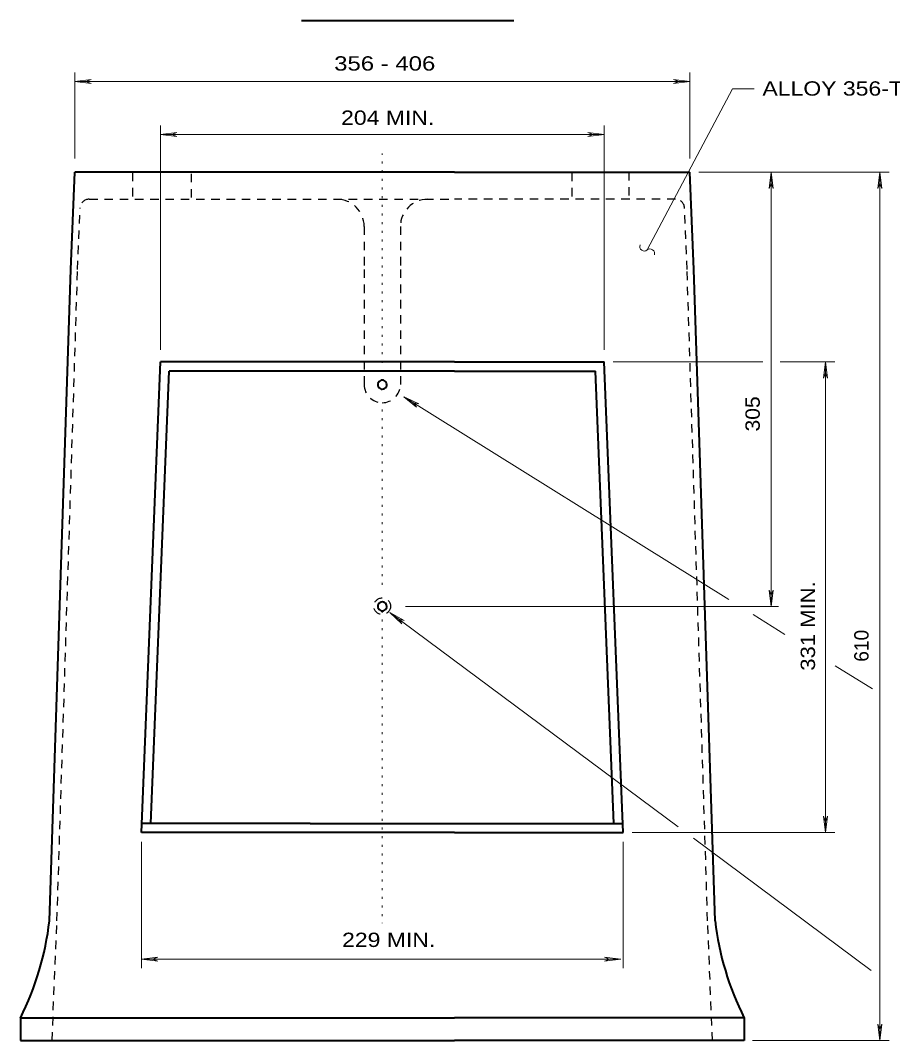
# Model space of a CAD drawing. Extents: x 312583 to 312854, y 144419 to 144597.
# Drawn here: x 312715.4 to 312761.7, y 144485 to 144539.1 of the extents above; entities that cross this region are included whole.
import ezdxf

# ---------------------------------------------------------------- set-up
doc = ezdxf.new("R2010")
doc.units = 0
doc.header["$LTSCALE"] = 0.3
doc.linetypes.add('DOTTED', pattern=[1.5, 0.3, -1.2])
doc.linetypes.add('SHORT_DASHED', pattern=[2.7, 1.5, -1.2])
doc.layers.add('1', color=7, linetype='Continuous', lineweight=40)
doc.layers.add('2', color=7, linetype='Continuous', lineweight=13)

msp = doc.modelspace()

# ---------------------------------------------------------------- linework, layer by layer
at = {"layer": '1'}
for p, q in [((312738.4, 144531.0452), (312718.2444, 144531.0452)), ((312738.4, 144531.0452), (312750.889, 144531.0452)), ((312721.7864, 144495.9932), (312722.7984, 144520.9712)), ((312738.4, 144520.9712), (312722.7984, 144520.9712)), ((312738.4, 144520.9712), (312746.335, 144520.9712)), ((312747.3547, 144495.9932), (312746.335, 144520.9712)), ((312722.2847, 144496.4686), (312723.2584, 144520.4882)), ((312738.4, 144520.4882), (312723.2584, 144520.4882)), ((312738.4, 144520.4882), (312745.875, 144520.4882)), ((312746.8487, 144496.4686), (312745.875, 144520.4882)), ((312730.7334, 144496.4686), (312721.8017, 144496.4686)), ((312730.7334, 144496.4686), (312747.3317, 144496.4686)), ((312738.4, 144495.9932), (312721.7864, 144495.9932)), ((312738.4, 144495.9932), (312747.3547, 144495.9932)), ((312715.3617, 144486.1569), (312715.3617, 144484.9532)), ((312715.3617, 144486.1569), (312738.4, 144486.1569)), ((312753.7717, 144486.1569), (312738.4, 144486.1569)), ((312753.7717, 144486.1569), (312753.7717, 144484.9532)), ((312715.3617, 144484.9532), (312738.4, 144484.9532)), ((312753.7717, 144484.9532), (312738.4, 144484.9532))]:
    msp.add_line(p, q, dxfattribs=at)
at = {"layer": '1', "linetype": 'SHORT_DASHED', "lineweight": 25}
for p, q in [((312721.265, 144531.0146), (312721.265, 144531.0452)), ((312721.311, 144531.0146), (312721.311, 144529.6116)), ((312724.4314, 144530.9609), (312724.4314, 144529.6116)), ((312744.6254, 144531.0146), (312744.6254, 144529.6116)), ((312747.646, 144531.0606), (312747.646, 144529.6116)), ((312719.011, 144529.6116), (312738.4, 144529.6116)), ((312750.13, 144529.6116), (312738.4, 144529.6116)), ((312718.3977, 144525.8856), (312718.528, 144529.1439)), ((312750.7434, 144525.8856), (312750.6054, 144529.1439))]:
    msp.add_line(p, q, dxfattribs=at)
at = {"layer": '1'}
for points in [[(312716.9027, 144491.3166), (312718.0374, 144525.8856), (312718.2444, 144531.0452)], [(312752.2307, 144491.3166), (312751.1037, 144525.8856), (312750.889, 144531.0452)]]:
    msp.add_lwpolyline(points, dxfattribs=at)
at = {"layer": '1', "linetype": 'SHORT_DASHED', "lineweight": 25}
for points in [[(312733.6084, 144528.1626), (312733.6084, 144525.8856), (312733.6084, 144519.7676)], [(312735.5327, 144528.1626), (312735.5327, 144525.8856), (312735.5327, 144519.7676)], [(312717.0407, 144484.9532), (312717.3014, 144491.3166), (312718.3977, 144525.8856)], [(312752.0927, 144484.9532), (312751.832, 144491.3166), (312750.7434, 144525.8856)]]:
    msp.add_lwpolyline(points, dxfattribs=at)
msp.add_circle((312734.5629, 144508.0069), 0.4408, dxfattribs=at)
for centre, radius, start, end in [((312719.0069, 144529.126), 0.4804, 90, 177.67414), ((312732.1656, 144528.1652), 1.4411, 0, 90), ((312736.9694, 144528.1652), 1.4411, 90, 180), ((312750.1281, 144529.126), 0.4804, 2.32586, 90), ((312734.5675, 144519.7682), 0.9608, 180, 270), ((312734.5648, 144519.7676), 0.9608, 270.11436, 0)]:
    msp.add_arc(centre, radius, start, end, dxfattribs=at)
at = {"layer": '1'}
for centre, radius, start, end in [((312734.5667, 144519.7676), 0.2402, 89.54164, 270.45836), ((312734.5667, 144519.7676), 0.2402, 270.45836, 91.37507), ((312734.5667, 144507.9973), 0.2402, 89.08692, 270.00364), ((312734.5667, 144507.9973), 0.2402, 270.00364, 90.92035), ((312701.6269, 144493.0588), 15.3723, 333.3018, 353.48942), ((312767.5065, 144493.0588), 15.3723, 186.51058, 206.6982)]:
    msp.add_arc(centre, radius, start, end, dxfattribs=at)
at = {"layer": '2', "lineweight": 40}
msp.add_line((312730.2713, 144539.099), (312741.5499, 144539.099), dxfattribs=at)
at = {"layer": '2'}
for p, q in [((312718.2444, 144531.7736), (312718.2444, 144536.3352)), ((312750.889, 144531.7736), (312750.889, 144536.3352)), ((312718.2444, 144535.8522), (312719.1107, 144535.9596)), ((312718.2444, 144535.8522), (312719.1107, 144535.7449)), ((312718.2444, 144535.8522), (312738.8754, 144535.8522)), ((312719.1107, 144535.9596), (312718.8347, 144535.8522)), ((312719.1107, 144535.7449), (312718.8347, 144535.8522)), ((312738.4, 144535.8522), (312750.889, 144535.8522)), ((312750.0227, 144535.9596), (312750.2987, 144535.8522)), ((312750.889, 144535.8522), (312750.0227, 144535.9596)), ((312750.0227, 144535.7449), (312750.2987, 144535.8522)), ((312750.889, 144535.8522), (312750.0227, 144535.7449)), ((312753.157, 144535.4673), (312748.6274, 144526.9206)), ((312753.157, 144535.4673), (312754.2993, 144535.4673)), ((312722.7984, 144533.0386), (312723.6647, 144533.1459)), ((312722.7984, 144533.0386), (312723.6647, 144532.9312)), ((312723.6647, 144533.1459), (312723.3887, 144533.0386)), ((312723.6647, 144532.9312), (312723.3887, 144533.0386)), ((312745.4687, 144533.1459), (312745.7447, 144533.0386)), ((312746.335, 144533.0386), (312745.4687, 144533.1459)), ((312745.4687, 144532.9312), (312745.7447, 144533.0386)), ((312746.335, 144533.0386), (312745.4687, 144532.9312)), ((312751.372, 144531.0452), (312761.4614, 144531.0452)), ((312755.213, 144531.0452), (312755.1057, 144530.1789)), ((312755.213, 144531.0452), (312755.3204, 144530.1789)), ((312760.9784, 144531.0452), (312760.871, 144530.1789)), ((312760.9784, 144531.0452), (312761.0857, 144530.1789)), ((312760.9784, 144525.8856), (312760.9784, 144531.0452)), ((312755.1057, 144530.1789), (312755.213, 144530.4549)), ((312755.3204, 144530.1789), (312755.213, 144530.4549)), ((312760.871, 144530.1789), (312760.9784, 144530.4549)), ((312761.0857, 144530.1789), (312760.9784, 144530.4549)), ((312760.9784, 144484.9532), (312760.9784, 144525.8856)), ((312746.818, 144520.9712), (312754.7684, 144520.9712)), ((312755.6807, 144520.9712), (312758.5787, 144520.9712)), ((312758.0957, 144520.9712), (312757.9884, 144520.1049)), ((312758.0957, 144495.9932), (312758.0957, 144520.9712)), ((312758.0957, 144520.9712), (312758.203, 144520.1049)), ((312757.9884, 144520.1049), (312758.0957, 144520.3809)), ((312758.203, 144520.1049), (312758.0957, 144520.3809)), ((312735.7167, 144519.1236), (312736.054, 144518.8476)), ((312735.7167, 144519.1236), (312736.1077, 144518.9396)), ((312735.7167, 144519.1236), (312736.3914, 144518.5716)), ((312735.7167, 144519.1236), (312736.5064, 144518.7556)), ((312752.9514, 144508.3672), (312735.7167, 144519.1236)), ((312736.054, 144518.8476), (312735.962, 144518.9702)), ((312736.1077, 144518.9396), (312735.962, 144518.9702)), ((312736.3914, 144518.5716), (312736.215, 144518.8092)), ((312736.5064, 144518.7556), (312736.215, 144518.8092)), ((312755.1057, 144508.8656), (312755.213, 144508.5896)), ((312755.213, 144507.9992), (312755.1057, 144508.8656)), ((312755.3204, 144508.8656), (312755.213, 144508.5896)), ((312755.213, 144507.9992), (312755.3204, 144508.8656)), ((312734.973, 144507.6772), (312735.6017, 144507.0716)), ((312734.973, 144507.6772), (312735.732, 144507.2479)), ((312750.2757, 144496.2922), (312734.973, 144507.6772)), ((312735.7934, 144507.9916), (312755.604, 144507.9916)), ((312755.9337, 144506.5119), (312754.2547, 144507.5622)), ((312735.6017, 144507.0716), (312735.4407, 144507.3246)), ((312735.732, 144507.2479), (312735.4407, 144507.3246)), ((312760.5797, 144503.6139), (312758.6017, 144504.8482)), ((312757.9884, 144496.8596), (312758.0957, 144496.5836)), ((312758.0957, 144495.9932), (312757.9884, 144496.8596)), ((312758.203, 144496.8596), (312758.0957, 144496.5836)), ((312758.0957, 144495.9932), (312758.203, 144496.8596)), ((312747.83, 144495.9932), (312758.5787, 144495.9932)), ((312760.5184, 144488.6716), (312751.0807, 144495.6942)), ((312721.7864, 144489.2772), (312722.6527, 144489.3846)), ((312721.7864, 144489.2772), (312722.6527, 144489.1699)), ((312721.7864, 144489.2772), (312741.9267, 144489.2772)), ((312722.6527, 144489.3846), (312722.3767, 144489.2772)), ((312722.6527, 144489.1699), (312722.3767, 144489.2772)), ((312738.4, 144489.2772), (312747.2244, 144489.2772)), ((312746.358, 144489.3846), (312746.634, 144489.2772)), ((312747.2244, 144489.2772), (312746.358, 144489.3846)), ((312746.358, 144489.1699), (312746.634, 144489.2772)), ((312747.2244, 144489.2772), (312746.358, 144489.1699)), ((312760.871, 144485.8196), (312760.9784, 144485.5436)), ((312760.9784, 144484.9532), (312760.871, 144485.8196)), ((312761.0857, 144485.8196), (312760.9784, 144485.5436)), ((312760.9784, 144484.9532), (312761.0857, 144485.8196)), ((312754.2087, 144484.9532), (312761.4767, 144484.9532))]:
    msp.add_line(p, q, dxfattribs=at)
at = {"layer": '2', "linetype": 'DOTTED'}
for p, q in [((312734.5667, 144520.9252), (312734.5667, 144532.0266)), ((312734.5667, 144509.1492), (312734.5667, 144518.8092)), ((312734.5667, 144507.7616), (312734.5667, 144491.1939))]:
    msp.add_line(p, q, dxfattribs=at)
at = {"layer": '2'}
for points in [[(312722.7984, 144521.6076), (312722.7984, 144525.8856), (312722.7984, 144533.5216)], [(312722.7984, 144533.0386), (312738.4, 144533.0386), (312746.335, 144533.0386)], [(312746.335, 144521.6076), (312746.335, 144525.8856), (312746.335, 144533.5216)], [(312755.213, 144507.9992), (312755.213, 144525.8856), (312755.213, 144531.0452)], [(312721.7864, 144495.5102), (312721.7864, 144491.3166), (312721.7864, 144488.7942)], [(312747.3547, 144495.5102), (312747.3547, 144491.3166), (312747.3547, 144488.7942)]]:
    msp.add_lwpolyline(points, dxfattribs=at)
for centre, start, end in [((312748.4707, 144527.0995), 160.267, 310.267), ((312748.7802, 144526.734), 340.267, 130.267)]:
    msp.add_arc(centre, 0.2395, start, end, dxfattribs=at)

# ---------------------------------------------------------------- texts
for s, width, p in [('356 - 406', 1.25, (312732.0126, 144536.4351)), ('ALLOY 356-T6', 1.2, (312754.7425, 144535.1062)), ('204 MIN.', 1.2, (312732.3801, 144533.5563)), ('229 MIN.', 1.2, (312732.4324, 144489.9206))]:
    msp.add_text(s, height=0.76, dxfattribs=dict(at, width=width)).set_placement(p)
for s, width, p in [('305', 1.1, (312754.6021, 144517.2812)), ('331 MIN.', 1.15, (312757.5336, 144504.586))]:
    msp.add_text(s, height=0.76, rotation=90, dxfattribs=dict(at, width=width)).set_placement(p)
msp.add_text('610', height=0.76, rotation=90, dxfattribs=at).set_placement((312760.375, 144505.0595))

doc.saveas('drawing.dxf')
